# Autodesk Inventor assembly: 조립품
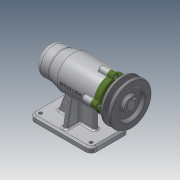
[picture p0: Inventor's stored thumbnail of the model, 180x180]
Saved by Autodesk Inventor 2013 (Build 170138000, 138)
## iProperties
Created: 2019-07
Part Number: 조립품
Document SubType Name: Assembly
Designer: 19
Author: 19
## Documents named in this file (12)
- C:\Users\19\Desktop\490704V1045\조립품.iam
- C:\Users\19\Desktop\490704V1045\본체.ipt
- C:\Users\19\Desktop\490704V1045\V벨트풀리.ipt
- C:\Users\19\Desktop\490704V1045\멈춤나사 M3.ipt
- C:\Users\19\Desktop\490704V1045\베어링 6004.ipt
- C:\Users\19\Desktop\490704V1045\베어링 51202.ipt
- C:\Users\19\Desktop\490704V1045\볼트 M4.ipt
- C:\Users\19\Desktop\490704V1045\어댑터슬리브.ipt
- C:\Users\19\Desktop\490704V1045\오일 실.ipt
- C:\Users\19\Desktop\490704V1045\축.ipt
- C:\Users\19\Desktop\490704V1045\커버.ipt
- C:\Users\19\Desktop\490704V1045\키 5 x 5 x 16.ipt
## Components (1 placed, 1 different names)
1. V벨트풀리:1
